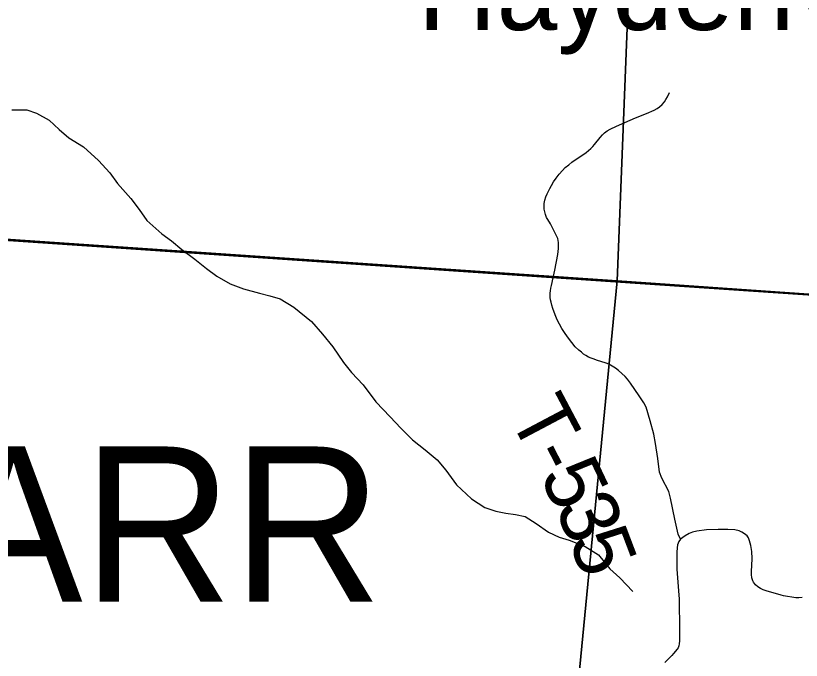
# Model space of a CAD drawing. Extents: x 0 to 34, y 0 to 22.
# Drawn here: x 5.957 to 6.717, y 18.417 to 19.04 of the extents above; entities that cross this region are included whole.
import ezdxf

# ---------------------------------------------------------------- set-up
doc = ezdxf.new("R2010")
doc.units = 0
for name, color, linetype in [('GM_X_Corporation', 7, 'Continuous'), ('GM_X_Minor_River', 7, 'Continuous'), ('GM_X_Township_Road', 7, 'Continuous'), ('GM_X_Township_Road_Text', 7, 'Continuous'), ('GM_X_Township_Text', 7, 'Continuous'), ('GM_X_Unincorporated_Text', 7, 'Continuous')]:
    doc.layers.add(name, color=color, linetype=linetype)

msp = doc.modelspace()

# ---------------------------------------------------------------- linework, layer by layer
at = {"layer": 'GM_X_Corporation'}
for points in [[(8.9, 18.63104), (8.9, 20.9), (3.64766, 20.9), (3.64639, 20.88271), (3.56651, 19.79699), (3.56604, 19.79055), (3.50701, 18.98834), (4.29309, 18.93502), (4.42098, 18.92635), (4.43616, 18.92532), (5.60032, 18.84635), (6.4706, 18.78732), (6.89502, 18.75853), (7.02554, 18.74968), (7.07142, 18.74657), (7.08445, 18.74568), (7.38896, 18.72502), (7.80881, 18.69655), (7.83532, 18.69516)], [(5.58553, 19.86463), (6.57976, 19.81144), (6.53912, 18.78352), (5.52629, 18.85259)], [(6.57976, 19.81144), (7.59407, 19.75829), (7.59584, 19.63858), (7.51615, 18.71572), (6.53912, 18.78352)], [(6.53912, 18.78352), (6.43864, 17.7441), (5.45917, 17.8072), (5.52629, 18.85259)], [(7.51615, 18.71572), (7.4643, 17.67029), (6.43864, 17.7441), (6.53912, 18.78352)]]:
    msp.add_lwpolyline(points, close=True, dxfattribs=at)
at = {"layer": 'GM_X_Minor_River'}
for p, q in [((5.9538, 18.94894), (5.96817, 18.94907)), ((5.96817, 18.94907), (5.97766, 18.94575)), ((5.97766, 18.94575), (5.98982, 18.93904)), ((5.98982, 18.93904), (5.99936, 18.93003)), ((5.99936, 18.93003), (6.00889, 18.92178)), ((6.00889, 18.92178), (6.02297, 18.91319)), ((6.02297, 18.91319), (6.03746, 18.90006)), ((6.03746, 18.90006), (6.04854, 18.88803)), ((6.04854, 18.88803), (6.05581, 18.87787)), ((6.05581, 18.87787), (6.06881, 18.86321)), ((6.06881, 18.86321), (6.07684, 18.85267)), ((6.07684, 18.85267), (6.08412, 18.84213)), ((6.08412, 18.84213), (6.09861, 18.82899)), ((6.09861, 18.82899), (6.10813, 18.82226)), ((6.10813, 18.82226), (6.11804, 18.81401)), ((6.11804, 18.81401), (6.13061, 18.80465)), ((6.13061, 18.80465), (6.14204, 18.79566)), ((6.14204, 18.79566), (6.15194, 18.78817)), ((6.15194, 18.78817), (6.16487, 18.78071)), ((6.16487, 18.78071), (6.17777, 18.7759)), ((6.17777, 18.7759), (6.19332, 18.77188)), ((6.19332, 18.77188), (6.20318, 18.76931)), ((6.20318, 18.76931), (6.21305, 18.76637)), ((6.21305, 18.76637), (6.22636, 18.75816)), ((6.22636, 18.75816), (6.24351, 18.74429)), ((6.24351, 18.74429), (6.25421, 18.73226)), ((6.25421, 18.73226), (6.26415, 18.71985)), ((6.26415, 18.71985), (6.2745, 18.70478)), ((6.2745, 18.70478), (6.28215, 18.695)), ((6.28215, 18.695), (6.2936, 18.68298)), ((6.2936, 18.68298), (6.30585, 18.6668)), ((6.30585, 18.6668), (6.3196, 18.65214)), ((6.3196, 18.65214), (6.32991, 18.64125)), ((6.32991, 18.64125), (6.34099, 18.62998)), ((6.34099, 18.62998), (6.35356, 18.62024)), ((6.35356, 18.62024), (6.36499, 18.61049)), ((6.36499, 18.61049), (6.3734, 18.60071)), ((6.3734, 18.60071), (6.38374, 18.58641)), ((6.38374, 18.58641), (6.39824, 18.5729)), ((6.39824, 18.5729), (6.41117, 18.56468)), ((6.41117, 18.56468), (6.4218, 18.56099)), ((6.4218, 18.56099), (6.43127, 18.55918)), ((6.43127, 18.55918), (6.44074, 18.55775)), ((6.44074, 18.55775), (6.45022, 18.55594)), ((6.45022, 18.55594), (6.46087, 18.54922)), ((6.46087, 18.54922), (6.47267, 18.54061)), ((6.47267, 18.54061), (6.48293, 18.53577)), ((6.48293, 18.53577), (6.4928, 18.53283)), ((6.4928, 18.53283), (6.50798, 18.52691)), ((6.50798, 18.52691), (6.52092, 18.51869)), ((6.52092, 18.51869), (6.53201, 18.50515)), ((6.53201, 18.50515), (6.54154, 18.49652)), ((6.54154, 18.49652), (6.55414, 18.48337))]:
    msp.add_line(p, q, dxfattribs=at)
at = {"layer": 'GM_X_Township_Road'}
for points in [[(6.60035, 18.53382), (6.59794, 18.53865), (6.59484, 18.55317), (6.5907, 18.5737), (6.5891, 18.58004), (6.58223, 18.59286), (6.58016, 18.59873), (6.57826, 18.61192), (6.57616, 18.62654), (6.57446, 18.63532), (6.5711, 18.64823), (6.56704, 18.66156), (6.56479, 18.66571), (6.56039, 18.6724), (6.55205, 18.68474), (6.54914, 18.68848), (6.54691, 18.69115), (6.54043, 18.69699), (6.53753, 18.69915), (6.53108, 18.70327), (6.52831, 18.70418), (6.51922, 18.70713), (6.51698, 18.70792), (6.51404, 18.70897), (6.51143, 18.71), (6.50877, 18.71138), (6.50654, 18.71286), (6.50446, 18.71456), (6.50189, 18.71665), (6.49848, 18.72001), (6.49534, 18.72405), (6.49198, 18.72827), (6.48866, 18.73287), (6.48562, 18.73771), (6.4832, 18.74179), (6.48173, 18.74473), (6.4804, 18.74767), (6.47903, 18.7509), (6.47689, 18.75678), (6.47589, 18.76005), (6.47509, 18.76301), (6.4746, 18.76532), (6.47432, 18.76752), (6.47422, 18.76961), (6.47431, 18.77176), (6.47456, 18.77412), (6.47503, 18.77668), (6.47555, 18.7791), (6.47891, 18.79398), (6.48172, 18.80917), (6.4821, 18.81198), (6.48234, 18.81487), (6.48243, 18.8171), (6.48239, 18.81913), (6.48225, 18.82088), (6.48196, 18.82274), (6.48156, 18.8245), (6.48115, 18.82587), (6.47471, 18.83886), (6.47199, 18.84295), (6.47077, 18.84505), (6.46972, 18.84764), (6.469, 18.85023), (6.46862, 18.85299), (6.46846, 18.85575), (6.46851, 18.8585), (6.46912, 18.86159), (6.47011, 18.86479), (6.47132, 18.86761), (6.47397, 18.87301), (6.47556, 18.87592), (6.47761, 18.8793), (6.48008, 18.88286), (6.48296, 18.88669), (6.48627, 18.89044), (6.48892, 18.89315), (6.49217, 18.8959), (6.49536, 18.89836), (6.50899, 18.90771), (6.51142, 18.90969), (6.51357, 18.91163), (6.51551, 18.91366), (6.5171, 18.91554), (6.52257, 18.92238), (6.52477, 18.92492), (6.52682, 18.92685), (6.52941, 18.92856), (6.53233, 18.93027), (6.53845, 18.93319), (6.55693, 18.9413), (6.56747, 18.94549), (6.57497, 18.94875), (6.57767, 18.95018), (6.57993, 18.95178), (6.58247, 18.95404), (6.58478, 18.95669), (6.58624, 18.95885), (6.58788, 18.9616), (6.5897, 18.96573)], [(6.71786, 18.4776), (6.71478, 18.47736), (6.71173, 18.47739), (6.70001, 18.47924), (6.69777, 18.47977), (6.68325, 18.4839), (6.68041, 18.48492), (6.67763, 18.48629), (6.67503, 18.48788), (6.67278, 18.48997), (6.67081, 18.49251), (6.67025, 18.49364), (6.66942, 18.49674), (6.66903, 18.49984), (6.669, 18.50299), (6.66931, 18.50835), (6.66953, 18.51512), (6.6692, 18.522), (6.66842, 18.52787), (6.66716, 18.53244), (6.66616, 18.53512), (6.66477, 18.53709), (6.66234, 18.53907), (6.65966, 18.5406), (6.65691, 18.5419), (6.65278, 18.54285), (6.64612, 18.54329), (6.6367, 18.54318), (6.62549, 18.54285), (6.61617, 18.54185), (6.61184, 18.54085), (6.60863, 18.53952), (6.60486, 18.53719), (6.60035, 18.53382), (6.59865, 18.53165), (6.59735, 18.52838), (6.59702, 18.52547), (6.59678, 18.52135), (6.59663, 18.50485), (6.5987, 18.47998), (6.59898, 18.47643), (6.59926, 18.44533), (6.59922, 18.43579), (6.59901, 18.43275), (6.59874, 18.43069), (6.5982, 18.42899), (6.59723, 18.4276), (6.59366, 18.42354), (6.59182, 18.42157), (6.58956, 18.4191), (6.58509, 18.41478)]]:
    msp.add_lwpolyline(points, dxfattribs=at)
at = {"layer": 'GM_X_Township_Text'}
msp.add_lwpolyline([(8.9, 18.63104), (7.83532, 18.69516), (7.80881, 18.69655), (7.38896, 18.72502), (7.08445, 18.74568), (7.07142, 18.74657), (7.02554, 18.74968), (6.89502, 18.75853), (6.4706, 18.78732), (5.60032, 18.84635), (4.43616, 18.92532), (4.42098, 18.92635), (4.29309, 18.93502), (3.50701, 18.98834), (3.39511, 17.26162), (3.35157, 16.58978), (3.30586, 15.8844), (3.28444, 15.55396), (3.23387, 14.77351), (3.19187, 14.12547), (3.19022, 14.1)], dxfattribs=at)

# ---------------------------------------------------------------- texts
at = {"layer": 'GM_X_Township_Road_Text'}
for s, rotation, p in [('T', 297.8819, (6.43336, 18.65335)), ('-', 297.18994, (6.45315, 18.61594)), ('5', 295.37341, (6.4636, 18.59561)), ('3', 293.18151, (6.47836, 18.56451)), ('5', 290.79055, (6.4919, 18.53292))]:
    msp.add_text(s, height=0.05682, rotation=rotation, dxfattribs=at).set_placement(p)
at = {"layer": 'GM_X_Township_Text'}
msp.add_text('STARR', height=0.15, rotation=0.00001, dxfattribs=at).set_placement((5.63208, 18.47356))
at = {"layer": 'GM_X_Unincorporated_Text'}
msp.add_text('Haydenville', height=0.0789773, rotation=0.00001, dxfattribs=at).set_placement((6.3463, 19.0262))

doc.saveas('drawing.dxf')
